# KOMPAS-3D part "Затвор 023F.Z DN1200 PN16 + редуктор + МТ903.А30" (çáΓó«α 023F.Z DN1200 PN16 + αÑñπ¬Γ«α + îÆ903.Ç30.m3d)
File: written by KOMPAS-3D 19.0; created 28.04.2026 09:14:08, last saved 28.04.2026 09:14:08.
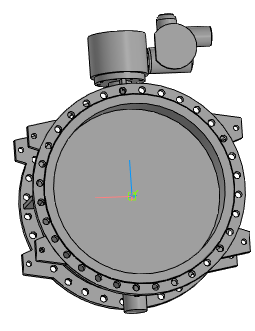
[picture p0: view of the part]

Document properties: Полное имя файла: ..\..\Затвор 023F.Z DN400-DN1600 + редуктор + МТ903\Затвор 023F.Z DN1200 PN16 + редуктор + МТ903.А30.a3d

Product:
- Part/product: Затвор 023F.Z DN1200 PN16 + редуктор + МТ903.А30
    Масса: 2367.05

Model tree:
1. Операция без истории:1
